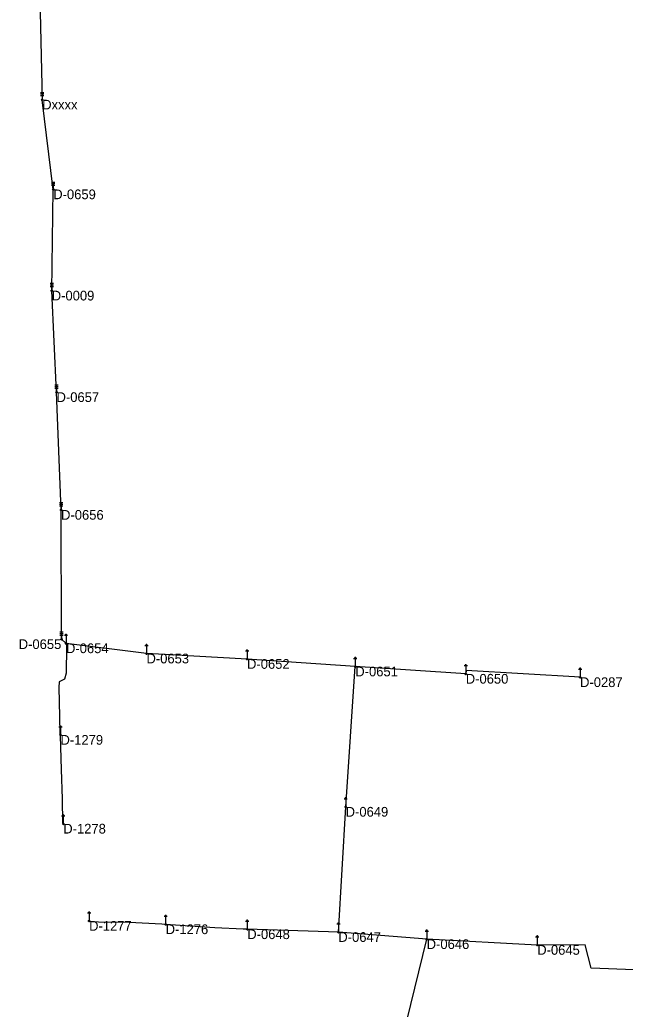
# Model space of a CAD drawing. Extents: x -729889 to -691139, y -995431 to -974354.
# Drawn here: x -725955 to -725767.9, y -979575.8 to -979270.2 of the extents above; entities that cross this region are included whole.
import ezdxf

# ---------------------------------------------------------------- set-up
doc = ezdxf.new("R2010")
doc.units = 0
for name, color, linetype in [('AES venkovní vedení', 7, 'Continuous'), ('Atributy', 7, 'Continuous'), ('Kabelové vedení VO', 7, 'Continuous'), ('Skutečně zaměřené kabelové vedení', 7, 'Continuous'), ('Světelný bod na stožáru jiného správce (ČEZ)', 7, 'Continuous'), ('Světelný bod na stožáru sadovém', 7, 'Continuous'), ('Venkovní vedení VO', 7, 'Continuous')]:
    doc.layers.add(name, color=color, linetype=linetype)

# ---------------------------------------------------------------- blocks, each defined once
blk = doc.blocks.new('6.571')
at = {"layer": 'Světelný bod na stožáru sadovém'}
for p, q in [((-0.51, 2.54), (0.51, 2.54)), ((0, 2.54), (0, 0.2))]:
    blk.add_line(p, q, dxfattribs=at)
for points in [[(0.25, 2.54), (0.25, 2.56), (0.25, 2.58), (0.24, 2.6), (0.24, 2.62), (0.23, 2.64), (0.22, 2.66), (0.21, 2.69), (0.19, 2.7), (0.18, 2.72), (0.16, 2.73), (0.15, 2.75), (0.13, 2.76), (0.11, 2.77), (0.09, 2.78), (0.07, 2.78), (0.05, 2.79), (0.02, 2.79), (0, 2.79), (-0.02, 2.79), (-0.05, 2.79), (-0.07, 2.78), (-0.09, 2.78), (-0.11, 2.77), (-0.13, 2.76), (-0.15, 2.75), (-0.16, 2.73), (-0.18, 2.72), (-0.19, 2.7), (-0.21, 2.69), (-0.22, 2.66), (-0.23, 2.64), (-0.24, 2.62), (-0.24, 2.6), (-0.25, 2.58), (-0.25, 2.56), (-0.25, 2.54)], [(-0.2, 0), (-0.17, -0.1), (-0.08, -0.18), (0.04, -0.19), (0.13, -0.14), (0.19, -0.05), (0.18, 0.07), (0.12, 0.15), (0.02, 0.19), (-0.09, 0.17), (-0.17, 0.09), (-0.18, -0.01), (-0.15, -0.1), (-0.06, -0.17), (0.04, -0.17), (0.12, -0.12), (0.17, -0.03), (0.16, 0.08), (0.1, 0.14), (0.01, 0.17), (-0.09, 0.14), (-0.15, 0.07), (-0.16, -0.01), (-0.12, -0.1), (-0.04, -0.15), (0.04, -0.15), (0.12, -0.1), (0.15, -0.01), (0.14, 0.07), (0.08, 0.13), (-0.01, 0.15), (-0.09, 0.12), (-0.13, 0.06), (-0.14, -0.02), (-0.1, -0.1), (-0.03, -0.13), (0.04, -0.13), (0.11, -0.08), (0.13, 0), (0.12, 0.07), (0.06, 0.12), (-0.02, 0.13), (-0.08, 0.1), (-0.12, 0.05), (-0.12, -0.03), (-0.08, -0.09), (-0.02, -0.11), (0.05, -0.11), (0.1, -0.06), (0.11, 0.01), (0.1, 0.06), (0.05, 0.11), (-0.02, 0.11), (-0.07, 0.09), (-0.1, 0.04), (-0.1, -0.03), (-0.06, -0.08), (-0.02, -0.1), (0.05, -0.08), (0.09, -0.04), (0.1, 0.01), (0.08, 0.06), (0.03, 0.09), (-0.02, 0.09), (-0.06, 0.07), (-0.08, 0.02), (-0.08, -0.03), (-0.05, -0.06), (-0.01, -0.08), (0.04, -0.06), (0.07, -0.03), (0.07, 0.01), (0.06, 0.05), (0.02, 0.07), (-0.02, 0.07), (-0.05, 0.05), (-0.07, 0.02), (-0.06, -0.03), (-0.04, -0.05), (0, -0.06), (0.04, -0.04), (0.05, -0.02), (0.06, 0.01), (0.04, 0.04), (0.01, 0.05), (-0.02, 0.05), (-0.04, 0.04), (-0.05, 0.01), (-0.04, -0.02), (-0.02, -0.03), (0.01, -0.04), (0.03, -0.03), (0.04, -0.01), (0.04, 0.01), (0.02, 0.03), (0.01, 0.04), (-0.01, 0.03), (-0.02, 0.02), (-0.03, 0.01), (-0.02, -0.01), (-0.01, -0.02)], [(-0.01, -0.02), (0.01, -0.02), (0.01, -0.01), (0.02, 0), (0.02, 0.01), (0.01, 0.02), (0, 0.02), (-0.01, 0.01), (-0.01, 0.01), (-0.01, 0.01)]]:
    blk.add_lwpolyline(points, dxfattribs=at)
blk.add_circle((0, 0), 0.203, dxfattribs=at)
blk = doc.blocks.new('5.25')
at = {"layer": 'Světelný bod na stožáru jiného správce (ČEZ)'}
for p, q in [((-0.5, 2.29), (0.5, 2.29)), ((-0.5, 1.79), (0.5, 1.79)), ((-0.5, 1.29), (0.5, 1.29)), ((0, 2.29), (0, 0.2))]:
    blk.add_line(p, q, dxfattribs=at)
for points in [[(-0.2, 0), (-0.17, -0.1), (-0.07, -0.18), (0.04, -0.18), (0.13, -0.14), (0.18, -0.04), (0.17, 0.07), (0.11, 0.15), (0.02, 0.19), (-0.09, 0.16), (-0.16, 0.08), (-0.18, 0), (-0.14, -0.1), (-0.05, -0.16), (0.04, -0.16), (0.12, -0.12), (0.17, -0.02), (0.15, 0.07), (0.1, 0.14), (0, 0.17), (-0.09, 0.14), (-0.14, 0.07), (-0.16, -0.01), (-0.12, -0.1), (-0.04, -0.15), (0.04, -0.14), (0.11, -0.1), (0.15, -0.01), (0.13, 0.07), (0.08, 0.13), (0, 0.15), (-0.08, 0.12), (-0.13, 0.06), (-0.14, -0.02), (-0.09, -0.09), (-0.03, -0.13), (0.04, -0.12), (0.1, -0.07), (0.13, 0), (0.11, 0.06), (0.06, 0.11), (-0.01, 0.13), (-0.08, 0.1), (-0.11, 0.04), (-0.12, -0.02), (-0.08, -0.08), (-0.02, -0.11), (0.04, -0.1), (0.09, -0.05), (0.11, 0), (0.09, 0.06), (0.04, 0.1), (-0.02, 0.11), (-0.07, 0.08), (-0.1, 0.03), (-0.09, -0.03), (-0.06, -0.07), (-0.01, -0.09), (0.04, -0.08), (0.08, -0.04), (0.09, 0), (0.07, 0.05), (0.03, 0.09), (-0.02, 0.09), (-0.06, 0.06), (-0.08, 0.02), (-0.07, -0.03), (-0.05, -0.06), (0, -0.07), (0.04, -0.06), (0.06, -0.03), (0.07, 0.01), (0.05, 0.05), (0.02, 0.07), (-0.01, 0.07), (-0.05, 0.05), (-0.06, 0.01), (-0.05, -0.02), (-0.03, -0.04), (0, -0.05), (0.03, -0.04), (0.05, -0.02), (0.05, 0.01), (0.04, 0.04), (0.01, 0.05), (-0.01, 0.05), (-0.03, 0.03), (-0.04, 0), (-0.04, -0.01), (-0.02, -0.03), (0, -0.03), (0.02, -0.02), (0.03, -0.01), (0.03, 0.01), (0.02, 0.02), (0, 0.03), (-0.01, 0.03), (-0.02, 0.02), (-0.02, 0), (-0.02, 0), (-0.01, -0.01)], [(-0.01, -0.01), (0, -0.01), (0.01, -0.01), (0.01, 0), (0.01, 0.01), (0.01, 0.01), (0, 0.01), (0, 0.01), (0, 0), (0, 0)]]:
    blk.add_lwpolyline(points, dxfattribs=at)
blk.add_circle((0, 0), 0.199, dxfattribs=at)

msp = doc.modelspace()

# ---------------------------------------------------------------- linework, layer by layer
at = {"layer": 'AES venkovní vedení'}
msp.add_line((-725948.89, -979260.88), (-725948.09, -979294.9), dxfattribs=at)
at = {"layer": 'Kabelové vedení VO'}
for p, q in [((-725940.73, -979462.84), (-725942.09, -979461.57)), ((-725884.78, -979467.68), (-725915.85, -979466)), ((-725851.32, -979470.01), (-725884.78, -979467.68)), ((-725854.3, -979513.35), (-725851.32, -979470.01)), ((-725817.18, -979472.26), (-725851.32, -979470.01)), ((-725856.56, -979552.05), (-725854.3, -979513.35)), ((-725856.56, -979552.05), (-725884.71, -979551.17)), ((-725829.26, -979554.24), (-725856.56, -979552.05)), ((-725835.42, -979579.39), (-725829.26, -979554.24)), ((-725795.1, -979556.02), (-725829.26, -979554.24))]:
    msp.add_line(p, q, dxfattribs=at)
for points in [[(-725915.85, -979466), (-725940.73, -979462.84), (-725940.56, -979463.87)], [(-725781.86, -979473.31), (-725817.02, -979471.19), (-725817.18, -979472.26)], [(-725765.11, -979563.72), (-725778.47, -979563.22), (-725780.33, -979555.95), (-725795.1, -979556.02)]]:
    msp.add_lwpolyline(points, dxfattribs=at)
at = {"layer": 'Skutečně zaměřené kabelové vedení'}
for points in [[(-725940.73, -979462.84), (-725940.56, -979463.87), (-725940.64, -979472.07), (-725941.22, -979473.91), (-725942.84, -979474.7), (-725942.92, -979476.44), (-725942.69, -979485.4), (-725942.6, -979490.98), (-725942.43, -979491.12)], [(-725942.43, -979491.12), (-725942.58, -979491.36), (-725942.21, -979501.84), (-725941.94, -979510.86), (-725941.8, -979518.4), (-725941.57, -979518.57)], [(-725909.93, -979549.64), (-725911.16, -979549.56), (-725921.16, -979549.11), (-725930.71, -979548.97), (-725932.96, -979548.87), (-725933.59, -979548.59)], [(-725884.71, -979551.17), (-725886.02, -979551.07), (-725894.77, -979550.66), (-725909.93, -979549.64)]]:
    msp.add_lwpolyline(points, dxfattribs=at)
at = {"layer": 'Venkovní vedení VO'}
for p, q in [((-725944.67, -979322.6), (-725948.09, -979294.9)), ((-725945.13, -979353.88), (-725944.67, -979322.6)), ((-725943.65, -979385.25), (-725945.13, -979353.88)), ((-725942.25, -979421.62), (-725943.65, -979385.25)), ((-725942.09, -979461.57), (-725942.25, -979421.62))]:
    msp.add_line(p, q, dxfattribs=at)

# ---------------------------------------------------------------- block references
at = {"layer": 'Světelný bod na stožáru jiného správce (ČEZ)', "xscale": 1.0049999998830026, "yscale": 1.0049999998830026}
for p in [(-725948.09, -979294.9), (-725944.67, -979322.6), (-725945.13, -979353.88), (-725943.65, -979385.25), (-725942.25, -979421.62), (-725942.09, -979461.57)]:
    msp.add_blockref('5.25', p, dxfattribs=at)
at = {"layer": 'Světelný bod na stožáru sadovém'}
for p, xscale, yscale in [((-725940.73, -979462.84), 1.0016949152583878, 1.0016949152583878), ((-725915.85, -979466), 1.0016949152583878, 1.0016949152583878), ((-725884.78, -979467.68), 1.0016949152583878, 1.0016949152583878), ((-725851.32, -979470.01), 1.0016949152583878, 1.0016949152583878), ((-725817.18, -979472.26), 1.0016949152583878, 1.0016949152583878), ((-725781.86, -979473.31), 1.0016949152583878, 1.0016949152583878), ((-725942.43, -979491.12), 0.9850000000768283, 0.9850000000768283), ((-725854.3, -979513.35), 1.0016949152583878, 1.0016949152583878), ((-725941.57, -979518.57), 0.9850000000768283, 0.9850000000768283), ((-725933.59, -979548.59), 0.9850000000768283, 0.9850000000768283), ((-725909.93, -979549.64), 0.9850000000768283, 0.9850000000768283), ((-725884.71, -979551.17), 1.0016949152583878, 1.0016949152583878), ((-725856.56, -979552.05), 1.0016949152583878, 1.0016949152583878), ((-725829.26, -979554.24), 1.0016949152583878, 1.0016949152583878), ((-725795.1, -979556.02), 1.0016949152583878, 1.0016949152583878)]:
    msp.add_blockref('6.571', p, dxfattribs=dict(at, xscale=xscale, yscale=yscale))

# ---------------------------------------------------------------- texts
at = {"layer": 'Atributy'}
for s, p in [('Dxxxx', (-725948.09, -979297.9)), ('D-0659', (-725944.67, -979325.61)), ('D-0009', (-725945.13, -979356.89)), ('D-0657', (-725943.65, -979388.26)), ('D-0656', (-725942.25, -979424.63)), ('D-0655', (-725955.34, -979464.58)), ('D-0654', (-725940.73, -979465.85)), ('D-0653', (-725915.85, -979469.01)), ('D-0652', (-725884.78, -979470.69)), ('D-0651', (-725851.32, -979473.02)), ('D-0650', (-725817.18, -979475.27)), ('D-0287', (-725781.86, -979476.32)), ('D-1279', (-725942.43, -979494.14)), ('D-0649', (-725854.3, -979516.36)), ('D-1278', (-725941.57, -979521.58)), ('D-1277', (-725933.59, -979551.6)), ('D-1276', (-725909.93, -979552.65)), ('D-0648', (-725884.71, -979554.18)), ('D-0647', (-725856.56, -979555.06)), ('D-0646', (-725829.26, -979557.25)), ('D-0645', (-725795.1, -979559.03))]:
    msp.add_text(s, height=3, dxfattribs=at).set_placement(p)

doc.saveas('drawing.dxf')
